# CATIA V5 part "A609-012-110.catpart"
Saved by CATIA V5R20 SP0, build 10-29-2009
Part number: A609-012-110
Source: Unknown
Property "ARTICLENO": "A609-012-110"
Property "B": "12.500"
Property "BOMINFO": "A609-012-110"
Property "CODE": "A609-012-110"
Property "D": "15.000"
Property "D1": "9.000"
Property "FORM": "A"
Property "L": "110.000"
Property "L1": "25.000"
Property "L2": "60.000"
Property "LINA": "A609-012-110"
Property "NB": "A609-012-110"
Property "NBSYN": "$CODE."
Property "NN": "A609"
Property "NT": "VDI 3357 E-Type Wear Plates, self-lubricating"
Property "S": "12.000"
Property "SUPPLIER": "CF"
Property "T": "8.500"
Property "W": "25.000"
Bounding box of the stored display mesh (mm): x 0 to 110, y 0 to 12, z 0 to 25
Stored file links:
  C:\Users\Utente\Desktop\3D files A609\A609-012-110.catpart
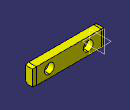
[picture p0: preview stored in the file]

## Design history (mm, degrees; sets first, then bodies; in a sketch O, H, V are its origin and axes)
Body1 "Geometry.1" (main body)
  Solid1 "A609-012-110.catpart": solid without history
